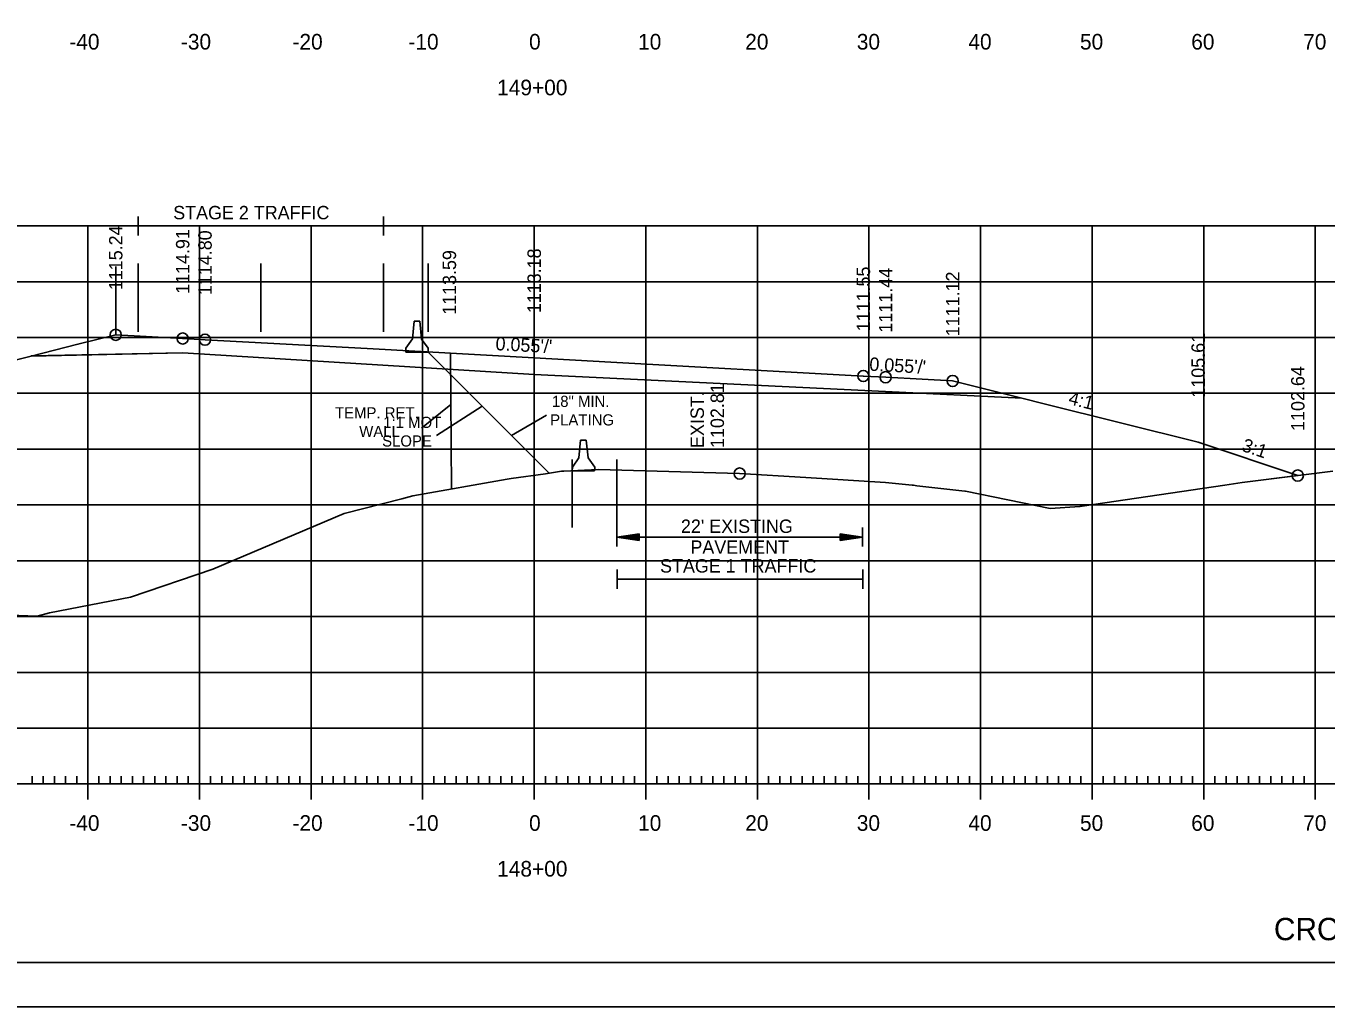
# Model space of a CAD drawing. Extents: x 1322838 to 1324533, y 339903 to 351025.
# Drawn here: x 1323668.2 to 1323784.7, y 343819.7 to 343907.6 of the extents above; entities that cross this region are included whole.
import ezdxf

# ---------------------------------------------------------------- set-up
doc = ezdxf.new("R2010")
doc.units = 0
for name, color, linetype in [('R_Alt Surface', 7, 'Continuous'), ('R_Axis', 7, 'Continuous'), ('R_Axis Annot', 7, 'Continuous'), ('R_Border', 7, 'Continuous'), ('R_Draft', 7, 'Continuous'), ('R_Exist Surface', 7, 'Continuous'), ('R_Fin Surface', 7, 'Continuous'), ('R_Fin Surface Annot', 7, 'Continuous'), ('R_Grid', 7, 'Continuous'), ('R_MOT', 7, 'Continuous'), ('R_No Plot', 7, 'Continuous'), ('R_Xsect Elev', 7, 'Continuous')]:
    doc.layers.add(name, color=color, linetype=linetype)

msp = doc.modelspace()

# ---------------------------------------------------------------- linework, layer by layer
at = {"layer": 'R_Alt Surface'}
msp.add_lwpolyline([(1323668.64, 343878.07), (1323682.22, 343878.34), (1323713.72, 343876.4), (1323745.21, 343874.87), (1323757.43, 343874.28)], dxfattribs=at)
at = {"layer": 'R_Axis'}
for p, q in [((1323668.72, 343839.72), (1323668.72, 343840.42)), ((1323669.72, 343839.72), (1323669.72, 343840.42)), ((1323670.72, 343839.72), (1323670.72, 343840.42)), ((1323671.72, 343839.72), (1323671.72, 343840.42)), ((1323672.72, 343839.72), (1323672.72, 343840.42)), ((1323673.72, 343838.32), (1323673.72, 343841.12)), ((1323674.72, 343839.72), (1323674.72, 343840.42)), ((1323675.72, 343839.72), (1323675.72, 343840.42)), ((1323676.72, 343839.72), (1323676.72, 343840.42)), ((1323677.72, 343839.72), (1323677.72, 343840.42)), ((1323678.72, 343839.72), (1323678.72, 343840.42)), ((1323679.72, 343839.72), (1323679.72, 343840.42)), ((1323680.72, 343839.72), (1323680.72, 343840.42)), ((1323681.72, 343839.72), (1323681.72, 343840.42)), ((1323682.72, 343839.72), (1323682.72, 343840.42)), ((1323683.72, 343838.32), (1323683.72, 343841.12)), ((1323684.72, 343839.72), (1323684.72, 343840.42)), ((1323685.72, 343839.72), (1323685.72, 343840.42)), ((1323686.72, 343839.72), (1323686.72, 343840.42)), ((1323687.72, 343839.72), (1323687.72, 343840.42)), ((1323688.72, 343839.72), (1323688.72, 343840.42)), ((1323689.72, 343839.72), (1323689.72, 343840.42)), ((1323690.72, 343839.72), (1323690.72, 343840.42)), ((1323691.72, 343839.72), (1323691.72, 343840.42)), ((1323692.72, 343839.72), (1323692.72, 343840.42)), ((1323693.72, 343838.32), (1323693.72, 343841.12)), ((1323694.72, 343839.72), (1323694.72, 343840.42)), ((1323695.72, 343839.72), (1323695.72, 343840.42)), ((1323696.72, 343839.72), (1323696.72, 343840.42)), ((1323697.72, 343839.72), (1323697.72, 343840.42)), ((1323698.72, 343839.72), (1323698.72, 343840.42)), ((1323699.72, 343839.72), (1323699.72, 343840.42)), ((1323700.72, 343839.72), (1323700.72, 343840.42)), ((1323701.72, 343839.72), (1323701.72, 343840.42)), ((1323702.72, 343839.72), (1323702.72, 343840.42)), ((1323703.72, 343838.32), (1323703.72, 343841.12)), ((1323704.72, 343839.72), (1323704.72, 343840.42)), ((1323705.72, 343839.72), (1323705.72, 343840.42)), ((1323706.72, 343839.72), (1323706.72, 343840.42)), ((1323707.72, 343839.72), (1323707.72, 343840.42)), ((1323708.72, 343839.72), (1323708.72, 343840.42)), ((1323709.72, 343839.72), (1323709.72, 343840.42)), ((1323710.72, 343839.72), (1323710.72, 343840.42)), ((1323711.72, 343839.72), (1323711.72, 343840.42)), ((1323712.72, 343839.72), (1323712.72, 343840.42)), ((1323713.72, 343838.32), (1323713.72, 343841.12)), ((1323714.72, 343839.72), (1323714.72, 343840.42)), ((1323715.72, 343839.72), (1323715.72, 343840.42)), ((1323716.72, 343839.72), (1323716.72, 343840.42)), ((1323717.72, 343839.72), (1323717.72, 343840.42)), ((1323718.72, 343839.72), (1323718.72, 343840.42)), ((1323719.72, 343839.72), (1323719.72, 343840.42)), ((1323720.72, 343839.72), (1323720.72, 343840.42)), ((1323721.72, 343839.72), (1323721.72, 343840.42)), ((1323722.72, 343839.72), (1323722.72, 343840.42)), ((1323723.72, 343838.32), (1323723.72, 343841.12)), ((1323724.72, 343839.72), (1323724.72, 343840.42)), ((1323725.72, 343839.72), (1323725.72, 343840.42)), ((1323726.72, 343839.72), (1323726.72, 343840.42)), ((1323727.72, 343839.72), (1323727.72, 343840.42)), ((1323728.72, 343839.72), (1323728.72, 343840.42)), ((1323729.72, 343839.72), (1323729.72, 343840.42)), ((1323730.72, 343839.72), (1323730.72, 343840.42)), ((1323731.72, 343839.72), (1323731.72, 343840.42)), ((1323732.72, 343839.72), (1323732.72, 343840.42)), ((1323733.72, 343838.32), (1323733.72, 343841.12)), ((1323734.72, 343839.72), (1323734.72, 343840.42)), ((1323735.72, 343839.72), (1323735.72, 343840.42)), ((1323736.72, 343839.72), (1323736.72, 343840.42)), ((1323737.72, 343839.72), (1323737.72, 343840.42)), ((1323738.72, 343839.72), (1323738.72, 343840.42)), ((1323739.72, 343839.72), (1323739.72, 343840.42)), ((1323740.72, 343839.72), (1323740.72, 343840.42)), ((1323741.72, 343839.72), (1323741.72, 343840.42)), ((1323742.72, 343839.72), (1323742.72, 343840.42)), ((1323743.72, 343838.32), (1323743.72, 343841.12)), ((1323744.72, 343839.72), (1323744.72, 343840.42)), ((1323745.72, 343839.72), (1323745.72, 343840.42)), ((1323746.72, 343839.72), (1323746.72, 343840.42)), ((1323747.72, 343839.72), (1323747.72, 343840.42)), ((1323748.72, 343839.72), (1323748.72, 343840.42)), ((1323749.72, 343839.72), (1323749.72, 343840.42)), ((1323750.72, 343839.72), (1323750.72, 343840.42)), ((1323751.72, 343839.72), (1323751.72, 343840.42)), ((1323752.72, 343839.72), (1323752.72, 343840.42)), ((1323753.72, 343838.32), (1323753.72, 343841.12)), ((1323754.72, 343839.72), (1323754.72, 343840.42)), ((1323755.72, 343839.72), (1323755.72, 343840.42)), ((1323756.72, 343839.72), (1323756.72, 343840.42)), ((1323757.72, 343839.72), (1323757.72, 343840.42)), ((1323758.72, 343839.72), (1323758.72, 343840.42)), ((1323759.72, 343839.72), (1323759.72, 343840.42)), ((1323760.72, 343839.72), (1323760.72, 343840.42)), ((1323761.72, 343839.72), (1323761.72, 343840.42)), ((1323762.72, 343839.72), (1323762.72, 343840.42)), ((1323763.72, 343838.32), (1323763.72, 343841.12)), ((1323764.72, 343839.72), (1323764.72, 343840.42)), ((1323765.72, 343839.72), (1323765.72, 343840.42)), ((1323766.72, 343839.72), (1323766.72, 343840.42)), ((1323767.72, 343839.72), (1323767.72, 343840.42)), ((1323768.72, 343839.72), (1323768.72, 343840.42)), ((1323769.72, 343839.72), (1323769.72, 343840.42)), ((1323770.72, 343839.72), (1323770.72, 343840.42)), ((1323771.72, 343839.72), (1323771.72, 343840.42)), ((1323772.72, 343839.72), (1323772.72, 343840.42)), ((1323773.72, 343838.32), (1323773.72, 343841.12)), ((1323774.72, 343839.72), (1323774.72, 343840.42)), ((1323775.72, 343839.72), (1323775.72, 343840.42)), ((1323776.72, 343839.72), (1323776.72, 343840.42)), ((1323777.72, 343839.72), (1323777.72, 343840.42)), ((1323778.72, 343839.72), (1323778.72, 343840.42)), ((1323779.72, 343839.72), (1323779.72, 343840.42)), ((1323780.72, 343839.72), (1323780.72, 343840.42)), ((1323781.72, 343839.72), (1323781.72, 343840.42)), ((1323782.72, 343839.72), (1323782.72, 343840.42)), ((1323783.72, 343838.32), (1323783.72, 343841.12)), ((1323563.72, 343839.72), (1323843.72, 343839.72))]:
    msp.add_line(p, q, dxfattribs=at)
at = {"layer": 'R_Axis Annot'}
for p, q in [((1323678.22, 343890.57), (1323678.22, 343888.87)), ((1323700.22, 343890.57), (1323700.22, 343888.87)), ((1323678.22, 343889.72), (1323700.22, 343889.72)), ((1323721.13, 343862.69), (1323721.13, 343860.98)), ((1323743.13, 343862.69), (1323743.13, 343860.98)), ((1323723.13, 343862.13), (1323721.13, 343861.83)), ((1323723.13, 343861.53), (1323721.13, 343861.83)), ((1323721.13, 343861.83), (1323743.13, 343861.83)), ((1323723.13, 343862.08), (1323721.47, 343861.83)), ((1323723.13, 343861.58), (1323721.47, 343861.83)), ((1323723.13, 343862.03), (1323721.81, 343861.83)), ((1323723.13, 343861.63), (1323721.81, 343861.83)), ((1323723.13, 343861.98), (1323722.14, 343861.83)), ((1323723.13, 343861.68), (1323722.14, 343861.83)), ((1323723.13, 343861.93), (1323722.48, 343861.83)), ((1323723.13, 343861.74), (1323722.48, 343861.83)), ((1323723.13, 343861.88), (1323722.82, 343861.83)), ((1323723.13, 343861.79), (1323722.82, 343861.83)), ((1323723.13, 343861.53), (1323723.13, 343862.13)), ((1323741.13, 343862.13), (1323743.13, 343861.83)), ((1323741.13, 343862.13), (1323741.13, 343861.53)), ((1323741.13, 343862.08), (1323742.8, 343861.83)), ((1323741.13, 343862.03), (1323742.46, 343861.83)), ((1323741.13, 343861.98), (1323742.12, 343861.83)), ((1323741.13, 343861.93), (1323741.78, 343861.83)), ((1323741.13, 343861.88), (1323741.45, 343861.83)), ((1323741.13, 343861.53), (1323743.13, 343861.83)), ((1323741.13, 343861.73), (1323741.78, 343861.83)), ((1323741.13, 343861.63), (1323742.46, 343861.83)), ((1323741.13, 343861.58), (1323742.8, 343861.83)), ((1323741.13, 343861.68), (1323742.12, 343861.83)), ((1323741.13, 343861.79), (1323741.45, 343861.83)), ((1323721.17, 343858.92), (1323721.17, 343857.21)), ((1323721.17, 343858.07), (1323743.17, 343858.07)), ((1323743.17, 343858.92), (1323743.17, 343857.21))]:
    msp.add_line(p, q, dxfattribs=at)
at = {"layer": 'R_Border'}
msp.add_line((1323861.9, 343823.72), (1323545.72, 343823.72), dxfattribs=at)
at = {"layer": 'R_Exist Surface'}
msp.add_lwpolyline([(1323666.7, 343854.84), (1323669.17, 343854.75), (1323670.29, 343855.04), (1323677.55, 343856.47), (1323684.93, 343858.96), (1323696.7, 343863.94), (1323701.86, 343865.28), (1323702.83, 343865.52), (1323711.29, 343867.02), (1323711.67, 343867.09), (1323714.74, 343867.52), (1323716.16, 343867.73), (1323716.39, 343867.74), (1323719.48, 343867.88), (1323728.92, 343867.62), (1323732.13, 343867.53), (1323738.05, 343867.17), (1323745.2, 343866.74), (1323747.58, 343866.49), (1323747.71, 343866.48), (1323748.01, 343866.44), (1323752.3, 343865.96), (1323752.38, 343865.94), (1323759.95, 343864.41), (1323762.62, 343864.59), (1323762.66, 343864.59), (1323762.82, 343864.62), (1323775.6, 343866.49), (1323777.17, 343866.72), (1323785.3, 343867.75)], dxfattribs=at)
at = {"layer": 'R_Fin Surface'}
msp.add_lwpolyline([(1323654.22, 343874.46), (1323668.64, 343878.06), (1323672.83, 343879.11), (1323676.22, 343879.96), (1323682.21, 343879.63), (1323682.22, 343879.63), (1323683.75, 343879.54), (1323684.22, 343879.52), (1323698.76, 343878.72), (1323713.71, 343877.9), (1323713.72, 343877.9), (1323720.58, 343877.52), (1323743.21, 343876.27), (1323743.22, 343876.27), (1323745.22, 343876.16), (1323748.48, 343875.98), (1323751.22, 343875.83), (1323757.43, 343874.28), (1323759.41, 343873.79), (1323773.22, 343870.33), (1323782.15, 343867.35)], dxfattribs=at)
at = {"layer": 'R_Grid'}
for p, q in [((1323563.72, 343889.72), (1323843.72, 343889.72)), ((1323673.72, 343839.72), (1323673.72, 343889.72)), ((1323683.72, 343839.72), (1323683.72, 343889.72)), ((1323693.72, 343839.72), (1323693.72, 343889.72)), ((1323703.72, 343839.72), (1323703.72, 343889.72)), ((1323713.72, 343839.72), (1323713.72, 343889.72)), ((1323723.72, 343839.72), (1323723.72, 343889.72)), ((1323733.72, 343839.72), (1323733.72, 343889.72)), ((1323743.72, 343839.72), (1323743.72, 343889.72)), ((1323753.72, 343839.72), (1323753.72, 343889.72)), ((1323763.72, 343839.72), (1323763.72, 343889.72)), ((1323773.72, 343839.72), (1323773.72, 343889.72)), ((1323783.72, 343839.72), (1323783.72, 343889.72)), ((1323563.72, 343884.72), (1323843.72, 343884.72)), ((1323563.72, 343879.72), (1323843.72, 343879.72)), ((1323563.72, 343874.72), (1323843.72, 343874.72)), ((1323563.72, 343869.72), (1323843.72, 343869.72)), ((1323563.72, 343864.72), (1323843.72, 343864.72)), ((1323563.72, 343859.72), (1323843.72, 343859.72)), ((1323563.72, 343854.72), (1323843.72, 343854.72)), ((1323563.72, 343849.72), (1323843.72, 343849.72)), ((1323563.72, 343844.72), (1323843.72, 343844.72)), ((1323563.72, 343839.72), (1323843.72, 343839.72))]:
    msp.add_line(p, q, dxfattribs=at)
at = {"layer": 'R_MOT'}
for p, q in [((1323702.8, 343879.59), (1323702.96, 343881.17)), ((1323703.21, 343881.17), (1323702.96, 343881.17)), ((1323703.46, 343881.17), (1323703.21, 343881.17)), ((1323703.63, 343879.58), (1323703.46, 343881.17)), ((1323702.22, 343878.75), (1323702.8, 343879.59)), ((1323704.22, 343878.75), (1323703.63, 343879.58)), ((1323702.21, 343878.42), (1323702.22, 343878.75)), ((1323704.22, 343878.42), (1323702.21, 343878.42)), ((1323704.22, 343878.42), (1323704.22, 343878.75)), ((1323706.25, 343873.72), (1323703.62, 343871.6)), ((1323717.72, 343868.94), (1323717.88, 343870.52)), ((1323718.13, 343870.52), (1323717.88, 343870.52)), ((1323718.38, 343870.52), (1323718.13, 343870.52)), ((1323718.55, 343868.94), (1323718.38, 343870.52)), ((1323717.14, 343868.11), (1323717.72, 343868.94)), ((1323719.14, 343868.11), (1323718.55, 343868.94)), ((1323717.13, 343867.77), (1323717.14, 343868.11)), ((1323719.13, 343867.77), (1323717.13, 343867.77)), ((1323719.13, 343867.77), (1323719.14, 343868.11))]:
    msp.add_line(p, q, dxfattribs=at)
msp.add_lwpolyline([(1323706.22, 343878.31), (1323706.31, 343866.14)], dxfattribs=at)
at = {"layer": 'R_No Plot'}
for p, q in [((1323676.22, 343886.08), (1323676.22, 343879.97)), ((1323678.22, 343886.34), (1323678.22, 343880.23)), ((1323689.22, 343886.34), (1323689.22, 343880.23)), ((1323700.22, 343886.34), (1323700.22, 343880.23)), ((1323704.22, 343886.34), (1323704.22, 343880.23)), ((1323704.22, 343878.42), (1323715.06, 343867.57)), ((1323704.98, 343870.93), (1323709.06, 343873.58)), ((1323714.82, 343872.77), (1323711.7, 343870.93)), ((1323717.13, 343868.79), (1323717.13, 343862.69)), ((1323721.13, 343868.79), (1323721.13, 343862.69)), ((1323533.31, 343819.74), (1323866.65, 343819.74))]:
    msp.add_line(p, q, dxfattribs=at)
for points in [[(1323533.31, 344033.07), (1323866.65, 344033.07), (1323866.65, 343819.74), (1323533.31, 343819.74)], [(1323779.64, 344029.18), (1323799.26, 344029.18), (1323799.26, 344019.3), (1323815.37, 344019.3), (1323838.57, 344019.3), (1323838.57, 343986.63), (1323861.77, 343986.63), (1323861.9, 343823.72), (1323545.72, 343823.72), (1323545.72, 344029.18)]]:
    msp.add_lwpolyline(points, close=True, dxfattribs=at)
msp.add_lwpolyline([(1323666.7, 343854.84), (1323669.17, 343854.75), (1323670.29, 343855.04), (1323677.55, 343856.47), (1323684.93, 343858.96), (1323696.7, 343863.94), (1323701.86, 343865.28), (1323702.83, 343865.52), (1323711.29, 343867.02), (1323711.67, 343867.09), (1323714.74, 343867.52), (1323716.16, 343867.73), (1323716.39, 343867.74), (1323719.48, 343867.88), (1323728.92, 343867.62), (1323732.13, 343867.53), (1323738.05, 343867.17), (1323745.2, 343866.74), (1323747.58, 343866.49), (1323747.71, 343866.48), (1323748.01, 343866.44), (1323752.3, 343865.96), (1323752.38, 343865.94), (1323759.95, 343864.41), (1323762.62, 343864.59), (1323762.66, 343864.59), (1323762.82, 343864.62), (1323775.6, 343866.49), (1323777.17, 343866.72), (1323782.15, 343867.35), (1323773.22, 343870.33), (1323759.41, 343873.79), (1323757.43, 343874.28), (1323745.21, 343874.87), (1323713.72, 343876.4), (1323682.22, 343878.34), (1323668.64, 343878.06), (1323654.22, 343874.46)], dxfattribs=at)
for centre in [(1323676.22, 343879.96), (1323682.22, 343879.63), (1323684.22, 343879.52), (1323743.22, 343876.27), (1323745.21, 343876.16), (1323751.22, 343875.83), (1323732.13, 343867.53), (1323782.15, 343867.35)]:
    msp.add_circle(centre, 0.5, dxfattribs=at)

# ---------------------------------------------------------------- texts
at = {"layer": 'R_Axis Annot'}
for s, height, p in [('-40', 1.4, (1323672.06, 343905.52)), ('-30', 1.4, (1323682.06, 343905.52)), ('-20', 1.4, (1323692.06, 343905.52)), ('-10', 1.4, (1323702.45, 343905.52)), ('0', 1.4, (1323713.26, 343905.52)), ('10', 1.4, (1323723.03, 343905.52)), ('20', 1.4, (1323732.63, 343905.52)), ('30', 1.4, (1323742.63, 343905.52)), ('40', 1.4, (1323752.63, 343905.52)), ('50', 1.4, (1323762.63, 343905.52)), ('60', 1.4, (1323772.6, 343905.52)), ('70', 1.4, (1323782.63, 343905.52)), ('149+00', 1.4, (1323710.4, 343901.42)), ('STAGE 2 TRAFFIC', 1.2, (1323681.37, 343890.31)), ("22' EXISTING ", 1.2, (1323726.87, 343862.21)), ('PAVEMENT', 1.2, (1323727.72, 343860.34)), ('STAGE 1 TRAFFIC', 1.2, (1323725, 343858.66)), ('-40', 1.4, (1323672.06, 343835.52)), ('-30', 1.4, (1323682.06, 343835.52)), ('-20', 1.4, (1323692.06, 343835.52)), ('-10', 1.4, (1323702.45, 343835.52)), ('0', 1.4, (1323713.26, 343835.52)), ('10', 1.4, (1323723.03, 343835.52)), ('20', 1.4, (1323732.63, 343835.52)), ('30', 1.4, (1323742.63, 343835.52)), ('40', 1.4, (1323752.63, 343835.52)), ('50', 1.4, (1323762.63, 343835.52)), ('60', 1.4, (1323772.6, 343835.52)), ('70', 1.4, (1323782.63, 343835.52)), ('148+00', 1.4, (1323710.4, 343831.42))]:
    msp.add_text(s, height=height, dxfattribs=at).set_placement(p)
at = {"layer": 'R_Draft'}
msp.add_text('CROSS SECTION STA. 148+00 TO STA. 149+00', height=2, dxfattribs=at).set_placement((1323780.01, 343825.72))
at = {"layer": 'R_Fin Surface Annot'}
for s, rotation, p in [('1115.24', 90, (1323676.82, 343883.96)), ('1114.91', 90, (1323682.82, 343883.63)), ('1114.80', 90, (1323684.82, 343883.52)), ('1113.18', 90, (1323714.32, 343881.9)), ('1111.55', 90, (1323743.82, 343880.27)), ('1111.44', 90, (1323745.81, 343880.16)), ('1111.12', 90, (1323751.82, 343879.83)), ('1105.61', 90, (1323773.82, 343874.33)), ("0.055'/'", 356.8519, (1323710.23, 343878.59)), ("0.055'/'", 356.8518, (1323743.73, 343876.75)), ('1102.64', 90, (1323782.75, 343871.35)), ('1102.64', 90, (1323782.75, 343871.35)), ('4:1', 345.9637, (1323761.53, 343873.77)), ('3:1', 341.5673, (1323777.05, 343869.58))]:
    msp.add_text(s, height=1.2, rotation=rotation, dxfattribs=at).set_placement(p)
at = {"layer": 'R_MOT'}
for s, p in [('TEMP. RET.', (1323695.87, 343872.47)), ('WALL', (1323698.04, 343870.8))]:
    msp.add_text(s, height=1, dxfattribs=at).set_placement(p)
at = {"layer": 'R_No Plot'}
msp.add_text('1113.59', height=1.2, rotation=90, dxfattribs=at).set_placement((1323706.72, 343881.75))
for s, p in [('18" MIN. ', (1323715.31, 343873.5)), ('1:1 MOT', (1323700.19, 343871.62)), ('PLATING', (1323715.15, 343871.84)), ('SLOPE', (1323700.09, 343869.95))]:
    msp.add_text(s, height=1, dxfattribs=at).set_placement(p)
at = {"layer": 'R_Xsect Elev'}
for s, p in [('1102.81', (1323730.73, 343869.82)), ('EXIST. ', (1323728.93, 343869.82))]:
    msp.add_text(s, height=1.2, rotation=90, dxfattribs=at).set_placement(p)

doc.saveas('drawing.dxf')
